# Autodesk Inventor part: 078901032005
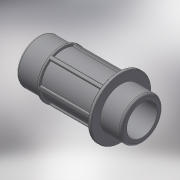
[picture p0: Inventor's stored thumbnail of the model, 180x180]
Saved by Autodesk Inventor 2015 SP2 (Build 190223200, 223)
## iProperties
Created: 2018-02
Part Number: 078901032005
Material: Generic
Description: PLASSON THREADED MALE ADAPTOR 32-1/2"
Document SubType Name: Modeling
Designer: KIM
Density: 1 g/cm^3
Appearance: Default
Author: KIM
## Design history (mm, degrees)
derived "078901.ipt"
feature "Solid1::078901.ipt"
tag "TaggingFeature1"
body "Solid1"
other parameters: "d4" = 1.04775, "d14" = 1.6764, "d15" = 0.8382, "d17" = 0, "d20" = 360 deg, "d40" = 17, "d41" = 20.955, "d45" = 23.0505, "d46" = 14.6685, "d47" = 1.7, "d77" = 85, "d78" = 32, "d85" = 0.20955, "d91" = 17, "d103" = 19.55, "d104" = 46, "d105" = 0.20955, "R_" = 20.955, "E_" = 46, "l_2" = 17, "l_" = 85, "d_" = 32
